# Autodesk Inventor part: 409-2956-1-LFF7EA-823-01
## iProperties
Created: 2010-11
Part Number: 409-2956-1-LFF7EA-823-01
Material: 3/8" OD TUBE - SS
Document SubType Name: Modeling
Designer: S. Boerckel
Engineer: Steve Boerckel
Mass: 314.256 g
Surface Area: 681.145 cm^2
Volume: 38.893 cm^3
Density: 8.08 g/cm^3
Description: PRESSURE DIFF TUBE
Length: 75.111 in
Author: S. Boerckel
Revision Number: 0
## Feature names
1. Sweep2
